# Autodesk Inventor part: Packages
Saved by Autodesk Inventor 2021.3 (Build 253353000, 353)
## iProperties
Created: 2023-03
Part Number: Packages
Material: Generic
Document SubType Name: Modeling
Designer: AdminForWorker
Density: 1 g/cm^3
Appearance: Default
Title: Packages
Author: AdminForWorker
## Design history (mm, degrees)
